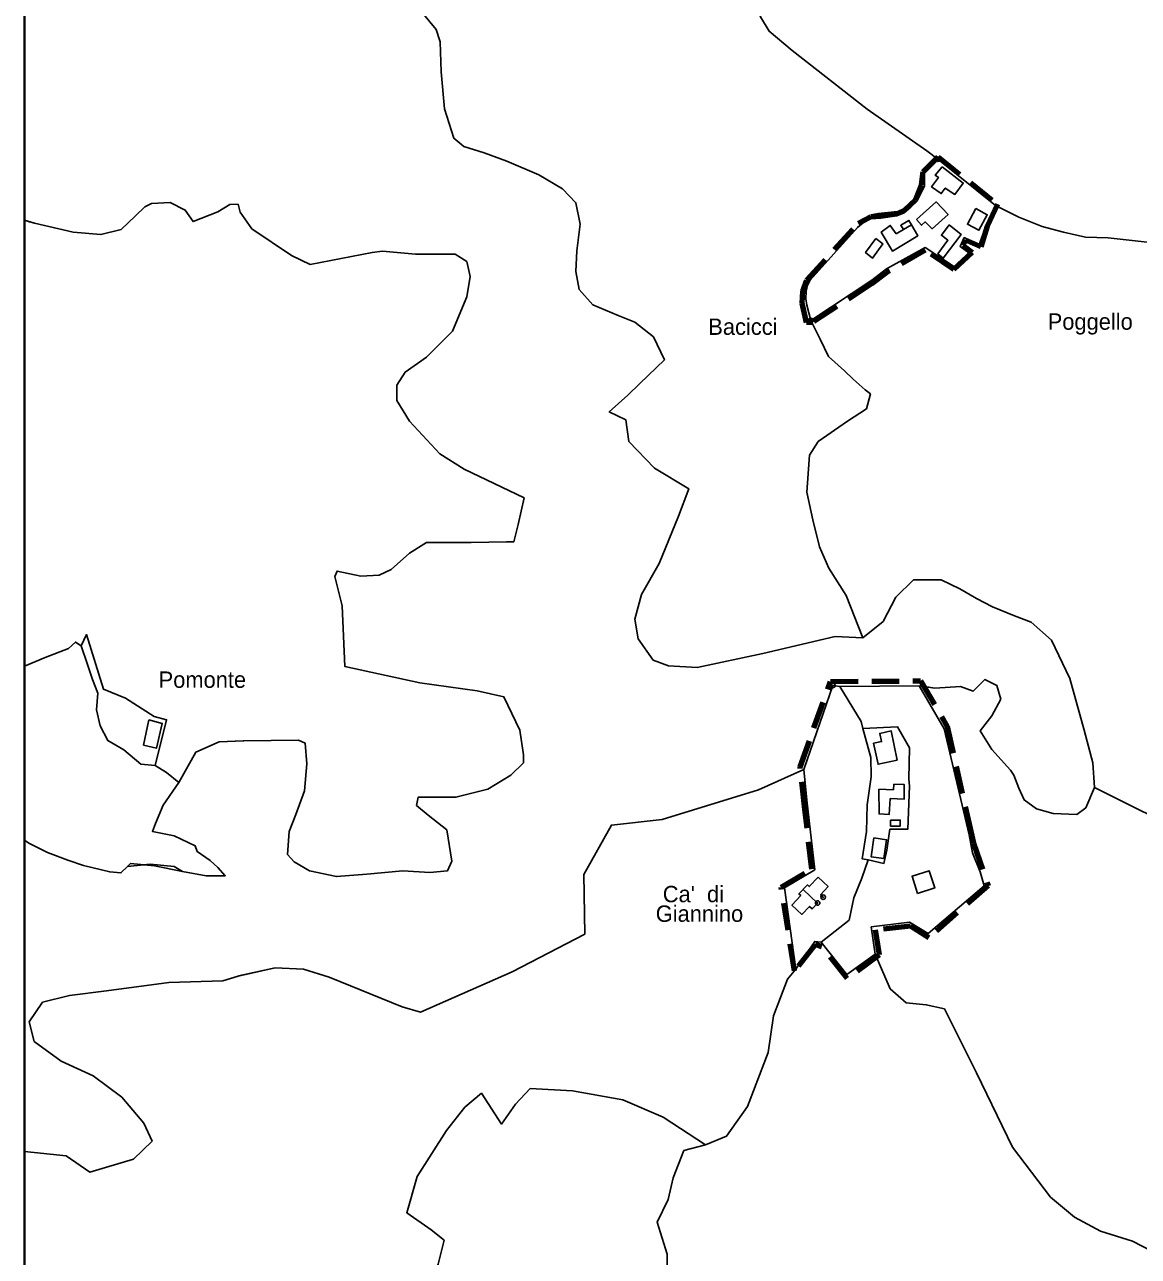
# Model space of a CAD drawing. Extents: x 652791 to 656927, y 889884 to 892405.
# Drawn here: x 654894 to 655576, y 890379 to 891133 of the extents above; entities that cross this region are included whole.
import ezdxf
from ezdxf.enums import TextEntityAlignment as Align

# ---------------------------------------------------------------- set-up
doc = ezdxf.new("R2010")
doc.units = 0
doc.header["$LTSCALE"] = 5.6
doc.header["$PDMODE"] = 32
doc.header["$PDSIZE"] = 2.8
doc.linetypes.add('MEDIUM_DASHED', pattern=[4.5, 3, -1.5])
for name, color, linetype, lineweight in [('1', 7, 'Continuous', 25), ('12', 7, 'Continuous', 25), ('35', 7, 'Continuous', 25), ('36', 7, 'Continuous', 25), ('37', 7, 'Continuous', 25), ('4', 7, 'Continuous', 25), ('6', 7, 'Continuous', 25), ('61', 7, 'Continuous', 35), ('7', 7, 'MEDIUM_DASHED', 100)]:
    doc.layers.add(name, color=color, linetype=linetype, lineweight=lineweight)
doc.layers.add('60', color=7, linetype='Continuous')

msp = doc.modelspace()

# ---------------------------------------------------------------- linework, layer by layer
at = {"layer": '1'}
for points in [[(655427.9, 891015.78), (655432.3, 891017.65), (655436.49, 891021.05), (655440.28, 891024.96), (655444.7, 891034.03), (655444.75, 891042.32), (655452.99, 891050.47), (655488.11, 891022.12), (655482.23, 891009.42), (655478.09, 890997.69), (655469.12, 891002.57), (655466.62, 890997.04)], [(655407.22, 891011.46), (655411.86, 891013.9), (655418.06, 891014.34), (655427.9, 891015.78)], [(655372.17, 890965.11), (655372.36, 890969.65), (655373.16, 890973.4), (655374.87, 890976.5), (655403.68, 891008.7), (655407.22, 891011.46)], [(655466.62, 890997.04), (655471.99, 890993.12), (655463.03, 890984.64), (655445.11, 890996.37), (655421.46, 890983.34), (655412.5, 890976.5), (655375.23, 890951.73)], [(655375.23, 890951.73), (655372.72, 890961.18), (655372.17, 890965.11)], [(655419.88, 890619.66), (655410.21, 890621.76), (655406.66, 890622.39), (655409.28, 890639.09), (655409.58, 890655.51), (655412.22, 890672.67), (655411.84, 890684.39), (655407.01, 890702.26), (655428.3, 890703.16), (655435.65, 890690.35)], [(655435.65, 890690.35), (655435.08, 890671.35), (655435.49, 890667), (655434.49, 890640.6), (655423.6, 890640.6), (655421.67, 890627.77), (655419.88, 890619.66)]]:
    msp.add_lwpolyline(points, dxfattribs=at)
for points in [[(655455.49, 891045.82), (655451.25, 891040.78), (655453.28, 891039.38), (655449.06, 891033.64), (655455.02, 891029.49), (655457.42, 891032.8), (655463.38, 891028.97), (655468.44, 891035.91)], [(655439.84, 891013.67), (655442.91, 891010.07), (655445.26, 891012.14), (655449.38, 891007.98), (655459.18, 891016.61), (655451.99, 891024.38)], [(655476.09, 891020.22), (655483.15, 891016.47), (655478.11, 891006.97), (655471.05, 891010.72)], [(655427.37, 891004.73), (655423.84, 891009.97), (655418.24, 891005.93), (655425.14, 890994.28), (655440.78, 891003.68), (655436.77, 891010.37), (655431.82, 891007.4)], [(655436.77, 891010.37), (655435.19, 891013), (655430.24, 891010.03), (655431.82, 891007.4)], [(655459.79, 891010.27), (655467.15, 891004.51), (655456.27, 890989.91), (655452.97, 890992.65), (655459.12, 891000.92), (655455.07, 891003.94)], [(655415.02, 891002.01), (655419.31, 890998.68), (655412.97, 890990.02), (655408.68, 890993.35)], [(655413.64, 890693.21), (655418.46, 890694.21), (655417.42, 890699.2), (655424.43, 890700.7), (655428.02, 890682.85), (655416.32, 890680.37)], [(655416.72, 890665.06), (655416.93, 890649.94), (655423.1, 890649.57), (655423.78, 890659.29), (655432.27, 890658.95), (655432.33, 890667.91), (655426, 890668.09), (655425.78, 890664.7)], [(655424.04, 890646.15), (655424.04, 890642.48), (655429.89, 890642.48), (655429.89, 890646.15)], [(655413.73, 890635.25), (655421.6, 890634.1), (655419.92, 890622.57), (655412.05, 890623.72)]]:
    msp.add_lwpolyline(points, close=True, dxfattribs=at)
msp.add_point((655375.23, 890951.73), dxfattribs=at)
at = {"layer": '12'}
for points in [[(655392.91, 890727.91), (655388.61, 890728.47), (655370.84, 890677.13), (655372.74, 890658.3)], [(655406.38, 890610.67), (655410.21, 890621.76), (655406.66, 890622.39), (655409.28, 890639.09), (655409.58, 890655.51), (655412.22, 890672.67), (655411.84, 890684.39), (655407.01, 890702.26), (655406.02, 890706.44), (655392.91, 890727.91)], [(655372.74, 890658.3), (655377.58, 890615.75), (655359.08, 890604.81), (655366, 890555.06), (655377.62, 890571.97), (655381.56, 890571.38), (655398.64, 890584.96), (655401.56, 890598.55), (655406.38, 890610.67)]]:
    msp.add_lwpolyline(points, dxfattribs=at)
msp.add_lwpolyline([(655381.56, 890571.38), (655397.3, 890551.65), (655414.58, 890564.19), (655412.21, 890580.81), (655435.65, 890583.75), (655447.03, 890576.71), (655481.25, 890606.01), (655478.74, 890614.51), (655474.08, 890626.21), (655472.03, 890637.14), (655456.86, 890701.91), (655441.49, 890728.27), (655392.91, 890727.91), (655406.02, 890706.44), (655407.01, 890702.26), (655428.3, 890703.16), (655435.65, 890690.35), (655435.65, 890690.35), (655435.08, 890671.35), (655435.49, 890667), (655434.49, 890640.6), (655423.6, 890640.6), (655421.67, 890627.77), (655419.88, 890619.66), (655410.21, 890621.76), (655406.38, 890610.67), (655401.56, 890598.55), (655398.64, 890584.96)], close=True, dxfattribs=at)
at = {"layer": '35'}
msp.add_lwpolyline([(655609.85, 890635.63), (655548.75, 890666.18), (655547.72, 890681.18), (655542.56, 890701.18), (655533.8, 890732.69), (655522.46, 890756.19), (655510.09, 890767.19), (655499.77, 890771.2), (655486.37, 890776.7), (655476.58, 890781.7), (655466.33, 890787.59), (655454.99, 890793.1), (655437.97, 890793.1), (655427.15, 890782.59), (655419.41, 890767.59), (655407.04, 890757.59), (655396.88, 890783.48), (655386.25, 890800.26), (655380.56, 890813.3), (655376.36, 890829.79), (655372.77, 890846.87), (655374.42, 890869.5), (655379.66, 890877.74), (655397.63, 890890.18), (655409.32, 890897.82), (655411.71, 890906.96), (655408.4, 890909.37), (655401.06, 890915.82), (655395.82, 890921.06), (655385.93, 890929.75), (655380.99, 890940.39), (655375.23, 890951.73), (655412.5, 890976.5), (655421.46, 890983.34), (655445.11, 890996.37), (655463.03, 890984.64), (655471.99, 890993.12), (655466.62, 890997.04), (655469.12, 891002.57), (655478.09, 890997.69), (655482.23, 891009.42), (655488.11, 891022.12), (655502.57, 891014.97), (655516.74, 891009.34), (655529.83, 891005.77), (655543.37, 891002.73), (655557.14, 891002.34), (655582.82, 890999.62)], dxfattribs=at)
at = {"layer": '36'}
for points in [[(655113.12, 890994.3), (655106.8, 890993.37), (655068.73, 890986.12), (655057.28, 890991.55), (655033.16, 891007.85), (655025.93, 891018.11), (655024.72, 891022.93), (655019.57, 891022.86), (655012.35, 891018.36), (654997.14, 891012.35), (654992.3, 891019.4), (654983.02, 891023.9), (654971.68, 891023.4), (654967.56, 891021.4), (654961.89, 891015.9), (654953.12, 891007.4), (654940.75, 891004.4), (654923.74, 891005.9), (654900.03, 891011.4), (654894.04, 891013.14), (654894.04, 891190.08)], [(655137.08, 891140.36), (655145.84, 891129.86), (655148.42, 891122.36), (655148.93, 891103.85), (655150.99, 891081.35), (655156.66, 891063.34), (655162.85, 891058.34), (655175.22, 891054.34), (655189.14, 891049.34), (655208.73, 891040.84), (655223.17, 891032.34), (655231.41, 891023.84), (655233.99, 891010.83), (655231.93, 890994.33), (655231.41, 890981.83), (655233.48, 890970.83), (655241.73, 890961.33), (655257.19, 890954.82), (655267.5, 890950.82), (655278.84, 890941.82), (655285.55, 890927.82), (655270.48, 890913.33), (655263.24, 890906.09), (655251.79, 890895.83), (655262.04, 890891), (655263.85, 890877.72), (655279.52, 890861.43)], [(655155.45, 890621.13), (655152.35, 890640.13), (655141.01, 890649.13), (655133.8, 890655.13), (655134.83, 890660.13), (655158.02, 890660.13), (655177.61, 890665.13), (655191.53, 890673.63), (655199.26, 890681.13), (655199.26, 890686.13), (655197.2, 890701.14), (655187.41, 890721.64), (655170.91, 890725.14), (655135.86, 890730.14), (655089.98, 890740.14), (655088.44, 890777.14), (655083.8, 890795.15), (655085.28, 890798.45), (655099.71, 890795.45), (655111.05, 890795.95), (655118.27, 890799.45), (655129.61, 890809.45), (655139.92, 890815.95), (655167.24, 890815.95), (655188.89, 890816.45), (655193.53, 890816.45), (655196.11, 890826.95), (655199.72, 890843.28), (655163.12, 890860.78), (655148.17, 890870.28), (655129.61, 890890.29), (655121.88, 890902.79), (655121.88, 890912.29), (655127.03, 890920.29), (655139.92, 890929.29), (655155.9, 890945.29), (655164.66, 890966.3), (655166.73, 890978.8), (655164.66, 890987.8), (655157.45, 890992.3)], [(655157.45, 890992.3), (655148.17, 890992.3), (655133.22, 890992.3), (655113.12, 890994.3)], [(655279.52, 890861.43), (655300.63, 890848.76), (655294.25, 890832.09), (655282.39, 890803.09), (655271.56, 890784.08), (655267.44, 890769.08), (655269.5, 890757.08), (655278.78, 890744.07), (655288.06, 890740.57), (655305.59, 890739.57), (655345.8, 890748.08), (655390.13, 890758.58), (655407.04, 890757.59), (655419.41, 890767.59), (655427.15, 890782.59), (655437.97, 890793.1), (655454.99, 890793.1), (655466.33, 890787.59), (655476.58, 890781.7), (655486.37, 890776.7), (655499.77, 890771.2), (655510.09, 890767.19), (655522.46, 890756.19), (655533.8, 890732.69), (655542.56, 890701.18), (655547.72, 890681.18), (655548.75, 890666.18), (655543.59, 890653.67), (655537.99, 890649.56), (655523.59, 890650.1), (655513.34, 890653.12), (655505.81, 890658.55), (655502.49, 890665.79), (655499.48, 890673.64), (655497.39, 890676.63), (655486, 890689.35), (655478.76, 890700.82), (655486, 890709.87), (655491.42, 890720.13), (655489.01, 890728.58)], [(655388.61, 890728.47), (655370.84, 890677.13), (655343.25, 890664.71), (655284.17, 890646.61), (655253.17, 890643.11), (655236.29, 890612.93), (655236.93, 890576.38), (655192.43, 890553.3), (655136.39, 890528.56), (655125, 890531.94), (655080.38, 890550.04), (655064.71, 890554.87), (655047.31, 890555.75), (655024.63, 890550.75), (655015.35, 890547.75), (654982.36, 890546.75), (654944.21, 890541.75), (654921.53, 890538.75), (654905.04, 890534.75), (654896.79, 890522.75), (654899.88, 890510.75), (654916.38, 890498.75), (654935.97, 890489.75), (654953.49, 890476.74), (654966.9, 890460.74), (654972.05, 890449.74), (654960.71, 890438.74), (654933.91, 890430.74), (654919.47, 890440.74), (654899.88, 890442.74), (654894.04, 890443.41), (654894.04, 890633.79)], [(655489.01, 890728.58), (655481.78, 890732.2), (655474.54, 890724.96), (655466.7, 890727.97), (655451.06, 890726.93), (655446.11, 890727.68), (655441.49, 890728.27), (655392.91, 890727.91), (655388.61, 890728.47)], [(654894.04, 890633.79), (654896.65, 890631.98), (654908.1, 890626.25), (654920.46, 890621.72), (654930.11, 890618.4), (654946.09, 890614.48), (654953.02, 890613.88), (654956.94, 890617.8), (654970.86, 890619.24), (654985.61, 890617.74), (654990.63, 890614.8), (655005.1, 890612.08), (655016.86, 890612.08), (655012.33, 890617.21), (655007.51, 890621.44), (654999.67, 890626.87), (654998.47, 890630.49), (654985.5, 890636.53), (654972.24, 890639.24), (654974.05, 890644.07), (654978.87, 890655.24), (654988.43, 890669.13), (654998.74, 890687.63), (655013.18, 890694.13), (655028.12, 890694.63), (655061.63, 890695.13), (655065.75, 890693.13), (655066.79, 890680.63), (655065.24, 890664.13), (655060.08, 890649.63), (655055.96, 890639.13), (655054.93, 890625.13), (655059.05, 890620.63), (655068.33, 890615.13), (655084.83, 890611.63), (655103.38, 890613.13), (655125.55, 890615.13), (655142.04, 890614.13), (655152.87, 890615.13), (655155.45, 890621.13)], [(655287.44, 890365.64), (655287.37, 890380.6), (655281.08, 890400.19), (655287.93, 890413.99), (655290.98, 890427.34), (655297.48, 890443.97), (655310.73, 890447.52), (655284.74, 890464.35), (655260.12, 890474.93), (655229.25, 890480.49), (655203.39, 890481.88), (655194.49, 890472.42), (655185.87, 890460.18), (655173.64, 890479.1)], [(655173.64, 890479.1), (655163.35, 890470.47), (655152.23, 890456.28), (655134.36, 890428.2), (655127.86, 890405.96), (655142.79, 890395.56), (655150.78, 890389.16), (655147.19, 890374.49), (655143.19, 890362.36)]]:
    msp.add_lwpolyline(points, dxfattribs=at)
msp.add_point((655388.61, 890728.47), dxfattribs=at)
at = {"layer": '37'}
for p, q in [((655137.08, 891140.36), (655145.84, 891129.86)), ((655145.85, 891129.86), (655148.43, 891122.36)), ((655453, 891050.47), (655446.28, 891055.67)), ((655452.99, 891050.47), (655488.11, 891022.12)), ((654894.04, 891013.14), (654894.04, 890740.32)), ((654894.04, 890443.41), (654894.04, 890376))]:
    msp.add_line(p, q, dxfattribs=at)
for points in [[(655326.07, 891229.86), (655338.47, 891220.11), (655351.99, 891216.87), (655372.17, 891200.77), (655361.89, 891190.13), (655354.57, 891194.25), (655349.54, 891194.25), (655346.89, 891188.94), (655341.73, 891191.31), (655336.12, 891181.8), (655334.94, 891173.54), (655336.12, 891160.58), (655344.36, 891137.59), (655349.67, 891128.75), (655363.8, 891116.96), (655409.75, 891081.01), (655446.27, 891055.66), (655452.99, 891050.47)], [(655349.67, 891128.75), (655344.37, 891137.59), (655336.12, 891160.58), (655334.94, 891173.54)], [(655446.27, 891055.66), (655409.75, 891081.01), (655363.8, 891116.96), (655349.67, 891128.75)], [(655148.42, 891122.36), (655148.93, 891103.85), (655150.99, 891081.35), (655156.66, 891063.34), (655162.85, 891058.34), (655175.22, 891054.34), (655189.14, 891049.34), (655208.73, 891040.84), (655223.17, 891032.34), (655231.41, 891023.84), (655233.99, 891010.83), (655231.93, 890994.33), (655231.41, 890981.83), (655233.48, 890970.83), (655241.73, 890961.33), (655257.19, 890954.82), (655267.5, 890950.82), (655278.84, 890941.82), (655285.55, 890927.82), (655270.48, 890913.33), (655263.24, 890906.09), (655251.79, 890895.83), (655262.04, 890891), (655263.85, 890877.72), (655279.52, 890861.43), (655300.63, 890848.76), (655294.25, 890832.09), (655282.39, 890803.09), (655271.56, 890784.08), (655267.44, 890769.08), (655269.5, 890757.08), (655278.78, 890744.07), (655288.06, 890740.57), (655305.59, 890739.57), (655345.8, 890748.08), (655390.13, 890758.58), (655407.04, 890757.59)], [(655427.9, 891015.78), (655432.3, 891017.65), (655436.49, 891021.05), (655440.28, 891024.96), (655444.7, 891034.03), (655444.75, 891042.32), (655452.99, 891050.47)], [(655113.12, 890994.3), (655106.8, 890993.37), (655068.73, 890986.12), (655057.28, 890991.55), (655033.16, 891007.85), (655025.93, 891018.11), (655024.72, 891022.93), (655019.57, 891022.86), (655012.35, 891018.36), (654997.14, 891012.35), (654992.3, 891019.4), (654983.02, 891023.9), (654971.68, 891023.4), (654967.56, 891021.4), (654961.89, 891015.9), (654953.12, 891007.4), (654940.75, 891004.4), (654923.74, 891005.9), (654900.03, 891011.4), (654897.08, 891012.26), (654894.04, 891013.14)], [(655488.11, 891022.12), (655502.57, 891014.96), (655516.74, 891009.33), (655529.83, 891005.76), (655543.36, 891002.72), (655557.14, 891002.33), (655582.81, 890999.61), (655609.01, 890994.87), (655611.84, 891011.93), (655617.48, 891020.1), (655637.34, 891020.1), (655654.68, 891018.08), (655670.8, 891013.54), (655673.43, 891008.6), (655669.7, 890999.12)], [(655407.22, 891011.46), (655411.86, 891013.9), (655418.06, 891014.34), (655427.9, 891015.78)], [(655372.17, 890965.11), (655372.36, 890969.65), (655373.16, 890973.4), (655374.87, 890976.5), (655403.68, 891008.7), (655407.22, 891011.46)], [(655197.2, 890701.14), (655187.41, 890721.64), (655170.91, 890725.14), (655135.86, 890730.14), (655089.98, 890740.14), (655088.44, 890777.14), (655083.8, 890795.15), (655085.28, 890798.45), (655099.71, 890795.45), (655111.05, 890795.95), (655118.27, 890799.45), (655129.61, 890809.45), (655139.92, 890815.95), (655167.24, 890815.95), (655188.89, 890816.45), (655193.53, 890816.45), (655196.11, 890826.95), (655199.72, 890843.28), (655163.12, 890860.78), (655148.17, 890870.28), (655129.61, 890890.29), (655121.88, 890902.79), (655121.88, 890912.29), (655127.03, 890920.29), (655139.92, 890929.29), (655155.9, 890945.29), (655164.66, 890966.3), (655166.73, 890978.8), (655164.66, 890987.8), (655157.45, 890992.3), (655148.17, 890992.3), (655133.22, 890992.3), (655113.12, 890994.3)], [(655375.23, 890951.73), (655372.72, 890961.18), (655372.17, 890965.11)], [(655407.04, 890757.59), (655396.88, 890783.48), (655386.25, 890800.26), (655380.56, 890813.3), (655376.36, 890829.79), (655372.77, 890846.87), (655374.42, 890869.5), (655379.66, 890877.74), (655397.63, 890890.18), (655409.32, 890897.82), (655411.71, 890906.96), (655408.4, 890909.37), (655401.06, 890915.82), (655395.82, 890921.06), (655385.93, 890929.75), (655380.99, 890940.39), (655375.23, 890951.73)], [(654920.82, 890751.04), (654925.17, 890755.02), (654928.59, 890752.77), (654931.89, 890759.67), (654942.38, 890726.17), (654955.87, 890720.67), (654973.39, 890709.56), (654980.89, 890707.55), (654973.86, 890679.66), (654980.82, 890675.37), (654988.43, 890669.13), (654998.74, 890687.63), (655013.18, 890694.13), (655027.82, 890694.62), (655028.12, 890694.63), (655061.63, 890695.13), (655065.75, 890693.13), (655066.79, 890680.63), (655065.24, 890664.13), (655060.08, 890649.63), (655055.96, 890639.13), (655054.93, 890625.13), (655059.05, 890620.63), (655068.33, 890615.13), (655084.83, 890611.63), (655103.38, 890613.13), (655125.55, 890615.13), (655142.04, 890614.13), (655152.87, 890615.13), (655155.45, 890621.13), (655152.35, 890640.13), (655141.01, 890649.13), (655133.8, 890655.13), (655134.83, 890660.13), (655158.02, 890660.13), (655177.61, 890665.13), (655191.53, 890673.63), (655199.26, 890681.13), (655199.26, 890686.13), (655197.2, 890701.14)], [(654928.59, 890752.77), (654925.17, 890755.02), (654920.82, 890751.04), (654906.7, 890745.6), (654894.04, 890740.32)], [(654894.04, 890740.32), (654906.7, 890745.6), (654920.82, 890751.04)], [(654988.43, 890669.13), (654980.82, 890675.37), (654973.86, 890679.66), (654965.07, 890680.35), (654954.82, 890689.1), (654944.87, 890694.83), (654940.35, 890703.88), (654937.94, 890713.54), (654938.84, 890723.8), (654935.53, 890732.25), (654932.51, 890741.3), (654928.59, 890752.77)], [(654894.04, 890740.32), (654894.04, 890633.79), (654896.65, 890631.98), (654897.08, 890631.77), (654908.08, 890626.26), (654908.1, 890626.25), (654920.46, 890621.72), (654930.11, 890618.4), (654946.09, 890614.48), (654953.02, 890613.88), (654956.94, 890617.8), (654958.75, 890619.61), (654973.5, 890618.11), (654990.63, 890614.8), (655005.1, 890612.08), (655016.86, 890612.08), (655012.33, 890617.21), (655007.51, 890621.44), (654999.67, 890626.87), (654998.47, 890630.49), (654985.5, 890636.53), (654972.24, 890639.24), (654974.05, 890644.07), (654978.87, 890655.24), (654988.43, 890669.13)], [(655646.5, 890637.96), (655631.75, 890636.44), (655609.85, 890635.63), (655548.75, 890666.18), (655543.59, 890653.67), (655537.99, 890649.56), (655523.59, 890650.1), (655513.34, 890653.12), (655505.81, 890658.55), (655502.49, 890665.79), (655499.48, 890673.64), (655497.39, 890676.63), (655486, 890689.35), (655478.76, 890700.82), (655486, 890709.87), (655491.42, 890720.13), (655489.01, 890728.58), (655481.78, 890732.2), (655474.54, 890724.96), (655466.7, 890727.97), (655451.06, 890726.93), (655441.49, 890728.27), (655456.86, 890701.91)], [(655456.86, 890701.91), (655472.03, 890637.14), (655474.08, 890626.21), (655478.74, 890614.51), (655481.25, 890606.01), (655447.03, 890576.71), (655435.65, 890583.75), (655412.21, 890580.81), (655414.58, 890564.19)], [(655366, 890555.06), (655359.08, 890604.81), (655377.58, 890615.75), (655372.74, 890658.3), (655370.84, 890677.13), (655343.25, 890664.71), (655284.17, 890646.61), (655253.17, 890643.11), (655236.29, 890612.93), (655236.93, 890576.38), (655192.43, 890553.3), (655136.39, 890528.56), (655125, 890531.94), (655080.38, 890550.04), (655064.71, 890554.87), (655047.31, 890555.75), (655027.82, 890551.45), (655024.87, 890550.8), (655024.63, 890550.75), (655015.35, 890547.75), (654982.36, 890546.75), (654944.21, 890541.75), (654921.53, 890538.75), (654905.04, 890534.75), (654896.79, 890522.75), (654899.88, 890510.75), (654916.38, 890498.75), (654935.97, 890489.75), (654953.49, 890476.74), (654966.9, 890460.74), (654972.05, 890449.74), (654960.71, 890438.74), (654933.91, 890430.74), (654919.47, 890440.74), (654899.88, 890442.74), (654894.04, 890443.41)], [(655414.58, 890564.19), (655397.3, 890551.65), (655381.56, 890571.38), (655377.62, 890571.97), (655366, 890555.06)], [(655414.58, 890564.19), (655423.83, 890542.98), (655433.63, 890534.4), (655445.88, 890533.18), (655456.91, 890530.73), (655476.51, 890491.5), (655498.56, 890446.15), (655521.83, 890415.51), (655536.53, 890403.25), (655552.45, 890394.67), (655572.05, 890388.55), (655583.86, 890382.52)], [(655583.86, 890382.52), (655572.05, 890388.55), (655552.45, 890394.67), (655536.53, 890403.25), (655521.83, 890415.51), (655498.56, 890446.15), (655476.51, 890491.5), (655456.91, 890530.73), (655445.88, 890533.18), (655433.63, 890534.4), (655423.83, 890542.98), (655414.58, 890564.19)], [(655366, 890555.06), (655360.9, 890548.75), (655352.37, 890526.34), (655349.17, 890503.93), (655336.37, 890470.85), (655323.57, 890452.71), (655310.73, 890447.52), (655297.48, 890443.97), (655290.98, 890427.34), (655287.93, 890413.99), (655281.08, 890400.19), (655287.37, 890380.6), (655287.44, 890365.64)], [(655310.73, 890447.52), (655323.57, 890452.71), (655336.37, 890470.85), (655349.17, 890503.93), (655352.37, 890526.34), (655360.9, 890548.75), (655366, 890555.06)], [(655152.23, 890456.28), (655163.35, 890470.47), (655173.64, 890479.1), (655185.87, 890460.18), (655194.49, 890472.42), (655203.39, 890481.88), (655229.25, 890480.49), (655260.12, 890474.93), (655284.74, 890464.35), (655310.73, 890447.52)], [(655061.02, 890359.53), (655097.56, 890343.86), (655138.98, 890333.95), (655142.59, 890355), (655143.19, 890362.36), (655147.19, 890374.49), (655150.78, 890389.16), (655142.79, 890395.56), (655127.86, 890405.96), (655134.36, 890428.2), (655152.23, 890456.28)]]:
    msp.add_lwpolyline(points, dxfattribs=at)
for p in [(655452.99, 891050.47), (655375.23, 890951.73)]:
    msp.add_point(p, dxfattribs=at)
at = {"layer": '4'}
for points in [[(654931.89, 890759.67), (654928.59, 890752.77), (654932.51, 890741.3), (654935.53, 890732.25), (654938.84, 890723.8), (654937.94, 890713.54), (654940.35, 890703.88), (654944.87, 890694.83), (654954.82, 890689.1), (654965.07, 890680.35), (654973.86, 890679.66), (654980.89, 890707.55), (654973.39, 890709.56), (654955.87, 890720.67), (654942.38, 890726.17)], [(654970.1, 890707.4), (654966.8, 890692.01), (654974.7, 890690.14), (654978.29, 890705.3)]]:
    msp.add_lwpolyline(points, close=True, dxfattribs=at)
at = {"layer": '6'}
msp.add_line((655370.56, 890603.74), (655379.36, 890595.43), dxfattribs=at)
msp.add_lwpolyline([(655440.53, 890601.3), (655450.99, 890604.71), (655447.57, 890615.17), (655437.11, 890611.76)], close=True, dxfattribs=at)
for points in [[(655379.36, 890595.43), (655375.99, 890591.86), (655374.39, 890593.38), (655369.72, 890588.43), (655363.62, 890594.2), (655369.04, 890599.95), (655367.95, 890600.98), (655373.17, 890606.5), (655374.26, 890605.47), (655379.69, 890611.21)], [(655379.69, 890611.21), (655385.79, 890605.44), (655381.12, 890600.5), (655382.72, 890598.99)]]:
    msp.add_lwpolyline(points, dxfattribs=at)
for p in [(655382.72, 890598.99), (655379.36, 890595.43)]:
    msp.add_point(p, dxfattribs=at)
at = {"layer": '61', "lineweight": 40}
msp.add_lwpolyline([(654894.04, 892404.68), (656926.84, 892404.68), (656926.84, 889884.41), (654894.04, 889884.41)], close=True, dxfattribs=at)
at = {"layer": '7'}
msp.add_lwpolyline([(655468.19, 890997.75), (655473.83, 890993.46), (655462.68, 890983.02), (655445.2, 890994.79), (655421.44, 890981.1), (655412.23, 890974.16), (655376.35, 890950.59), (655372.51, 890950.57), (655369.93, 890962.31), (655370.3, 890969.71), (655372.81, 890976.56), (655404.27, 891011.27), (655412.21, 891015.47), (655416.67, 891016.17), (655428.49, 891017.47), (655432.74, 891019.54), (655439.21, 891025.65), (655442.95, 891034.77), (655443.96, 891042.82), (655453.12, 891051.84), (655489.48, 891022.93), (655483.11, 891009.56), (655479.22, 890996.81), (655469.9, 891001.01)], close=True, dxfattribs=at)
for points in [[(655365.21, 890553.86), (655357.09, 890605.05), (655375.78, 890616.12), (655371.54, 890652.78), (655368.66, 890678.78), (655387.28, 890731.03), (655442.4, 890731.3), (655458.67, 890703.46)], [(655458.67, 890703.46), (655472.06, 890643.59), (655474.68, 890632.04), (655483.74, 890606.03), (655447.35, 890574.04)], [(655447.35, 890574.04), (655436.28, 890581.18), (655414.64, 890578.96), (655417.1, 890563.71)], [(655417.1, 890563.71), (655397.42, 890549.19), (655381.93, 890568.63), (655377.99, 890570.1), (655365.21, 890553.86)]]:
    msp.add_lwpolyline(points, dxfattribs=at)

# ---------------------------------------------------------------- texts
at = {"layer": '60'}
for s, p in [('Poggello', (655546.19, 890946.16)), ('Bacicci', (655333.62, 890943.01)), ('Pomonte', (655002.81, 890727.08)), ("Ca'  di  ", (655307.04, 890595.92)), ('Giannino', (655307.04, 890583.92))]:
    msp.add_text(s, height=10, dxfattribs=at).set_placement(p, align=Align.CENTER)

doc.saveas('drawing.dxf')
